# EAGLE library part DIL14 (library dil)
SOCKET Dual In Line
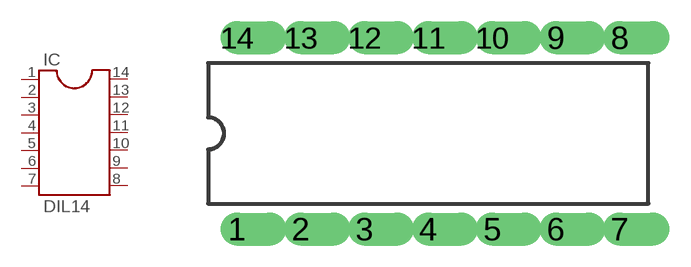
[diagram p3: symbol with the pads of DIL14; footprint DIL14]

Designator prefix IC

## DIL14  [DIL14]
1  1  pas
2  2  pas
3  3  pas
4  4  pas
5  5  pas
6  6  pas
7  7  pas
8  8  pas
9  9  pas
10  10  pas
11  11  pas
12  12  pas
13  13  pas
14  14  pas

## Footprint DIL14 (pad centres in mm)
SOCKET Dual In Line
drill 0.813 offset: 1 -7.62,-3.81; 2 -5.08,-3.81; 3 -2.54,-3.81; 4 0,-3.81; 5 2.54,-3.81; 6 5.08,-3.81; 7 7.62,-3.81; 8 7.62,3.81; 9 5.08,3.81; 10 2.54,3.81; 11 0,3.81; 12 -2.54,3.81; 13 -5.08,3.81; 14 -7.62,3.81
